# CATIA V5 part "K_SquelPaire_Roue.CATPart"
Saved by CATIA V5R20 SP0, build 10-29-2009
Part number: squelette_paire_roue
Publications: "entraxe_roue", "Sommet", "Plan.5", "Sommet1", "Plan.6"
Bounding box of the stored display mesh (mm): x -138 to 62, y 182.128 to 182.128, z -194.454 to -194.454
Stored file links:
  G:\Khaled_CFAO_2011\ST2M\ST2M_GR2\plakomicki\Khaled\CAD_ThinkMOTION\K_SquelPaire_Roue.CATPart
  G:\Khaled_CFAO_2011\ST2M\ST2M_GR2\plakomicki\Khaled\CAD_ThinkMOTION\K_Jambe.CATProduct
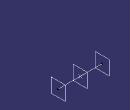
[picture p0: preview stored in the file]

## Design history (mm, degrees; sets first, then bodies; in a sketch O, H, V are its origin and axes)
Parameters
  entraxe_roue = 200 mm
Set1
  Point1: linked copy from another document
  Plane1: linked copy from another document
Body1 (main body)
  Line1: type PtDir, RefPoint Point1, Direction Plane1, Start -100, End 100 {= entraxe_roue /2}
  Plane2: type OffsetPt, RefPlane yz-plane, RefPoint vertex of Line1
  Plane3: type OffsetPt, RefPlane yz-plane, RefPoint vertex of Line1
